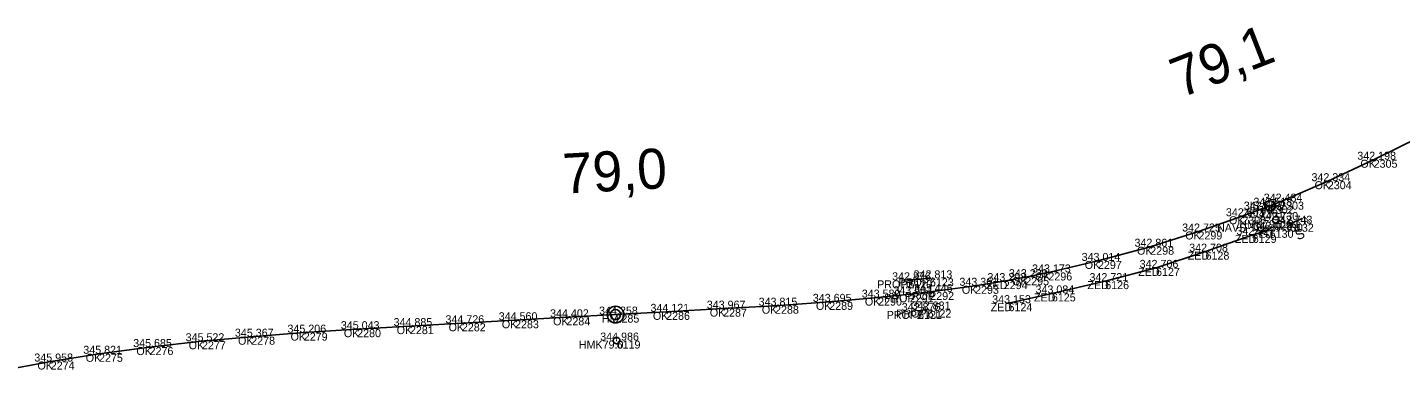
# Model space of a CAD drawing. Extents: x -621782 to -610392, y -1141853 to -1122321.
# Drawn here: x -615402.5 to -615196.7, y -1130069.9 to -1130018.3 of the extents above; entities that cross this region are included whole.
import ezdxf

# ---------------------------------------------------------------- set-up
doc = ezdxf.new("R2010")
doc.units = 0
for name, color, linetype in [('Vrstva 1', 7, 'Continuous'), ('Vrstva 13', 7, 'Continuous'), ('Vrstva 19', 7, 'Continuous'), ('Vrstva 6', 7, 'Continuous'), ('Vrstva 60', 7, 'Continuous'), ('Vrstva 61', 7, 'Continuous'), ('Vrstva 62', 7, 'Continuous'), ('Vrstva 7', 7, 'Continuous')]:
    doc.layers.add(name, color=color, linetype=linetype)

msp = doc.modelspace()

# ---------------------------------------------------------------- linework, layer by layer
at = {"layer": 'Vrstva 1'}
msp.add_lwpolyline([(-615407.12, -1130069.91), (-615399.04, -1130068.4), (-615391.8, -1130067.24), (-615384.22, -1130066.23), (-615376.37, -1130065.36), (-615368.98, -1130064.68), (-615361.1, -1130064.07), (-615353.1, -1130063.55), (-615345.19, -1130063.09), (-615337.4, -1130062.66), (-615329.43, -1130062.21), (-615321.73, -1130061.77), (-615314.37, -1130061.36), (-615306.78, -1130060.95), (-615298.24, -1130060.47), (-615290.45, -1130060.03), (-615282.33, -1130059.45), (-615275, -1130058.81), (-615270.25, -1130058.31), (-615267.18, -1130057.97), (-615260.46, -1130057.04), (-615256.16, -1130056.34), (-615252.94, -1130055.75), (-615249.47, -1130055.04), (-615242.04, -1130053.31), (-615234.2, -1130051.18), (-615226.97, -1130048.9), (-615220.41, -1130046.61), (-615217.74, -1130045.61), (-615216.28, -1130045.04), (-615214.73, -1130044.42), (-615207.58, -1130041.35), (-615200.71, -1130038.13), (-615193.76, -1130034.67)], dxfattribs=at)
at = {"layer": 'Vrstva 13'}
msp.add_lwpolyline([(-615216.29, -1130048.64), (-615218.84, -1130049.41), (-615225.91, -1130051.92), (-615233.33, -1130054.35), (-615240.95, -1130056.34), (-615248.95, -1130058.18), (-615255.45, -1130059.65)], dxfattribs=at)
at = {"layer": 'Vrstva 19'}
for p, q in [((-615270.45, -1130056.22), (-615267.23, -1130055.92)), ((-615269.01, -1130060.81), (-615267.59, -1130060.6))]:
    msp.add_line(p, q, dxfattribs=at)
at = {"layer": 'Vrstva 6'}
for p, q in [((-615211.43, -1130046.95), (-615213.25, -1130047.73)), ((-615213.45, -1130047.27), (-615213.05, -1130048.19))]:
    msp.add_line(p, q, dxfattribs=at)
at = {"layer": 'Vrstva 60'}
for p, q in [((-615200.71, -1130038.13), (-615200.71, -1130038.13)), ((-615207.58, -1130041.35), (-615207.58, -1130041.35)), ((-615216.28, -1130045.04), (-615216.28, -1130045.04)), ((-615214.73, -1130044.42), (-615214.73, -1130044.42)), ((-615220.41, -1130046.61), (-615220.41, -1130046.61)), ((-615217.74, -1130045.61), (-615217.74, -1130045.61)), ((-615226.97, -1130048.9), (-615226.97, -1130048.9)), ((-615216.29, -1130048.64), (-615216.29, -1130048.64)), ((-615215.37, -1130047.18), (-615215.37, -1130047.18)), ((-615213.25, -1130047.73), (-615213.25, -1130047.73)), ((-615234.2, -1130051.18), (-615234.2, -1130051.18)), ((-615218.84, -1130049.41), (-615218.84, -1130049.41)), ((-615242.04, -1130053.31), (-615242.04, -1130053.31)), ((-615225.91, -1130051.92), (-615225.91, -1130051.92)), ((-615249.47, -1130055.04), (-615249.47, -1130055.04)), ((-615233.33, -1130054.35), (-615233.33, -1130054.35)), ((-615270.45, -1130056.22), (-615270.45, -1130056.22)), ((-615267.23, -1130055.92), (-615267.23, -1130055.92)), ((-615260.46, -1130057.04), (-615260.46, -1130057.04)), ((-615256.16, -1130056.34), (-615256.16, -1130056.34)), ((-615252.94, -1130055.75), (-615252.94, -1130055.75)), ((-615240.95, -1130056.34), (-615240.95, -1130056.34)), ((-615282.33, -1130059.45), (-615282.33, -1130059.45)), ((-615275, -1130058.81), (-615275, -1130058.81)), ((-615270.25, -1130058.31), (-615270.25, -1130058.31)), ((-615267.18, -1130057.97), (-615267.18, -1130057.97)), ((-615248.95, -1130058.18), (-615248.95, -1130058.18)), ((-615314.37, -1130061.36), (-615314.37, -1130061.36)), ((-615306.78, -1130060.95), (-615306.78, -1130060.95)), ((-615298.24, -1130060.47), (-615298.24, -1130060.47)), ((-615290.45, -1130060.03), (-615290.45, -1130060.03)), ((-615269.01, -1130060.81), (-615269.01, -1130060.81)), ((-615267.59, -1130060.6), (-615267.59, -1130060.6)), ((-615255.45, -1130059.65), (-615255.45, -1130059.65)), ((-615353.1, -1130063.55), (-615353.1, -1130063.55)), ((-615345.19, -1130063.09), (-615345.19, -1130063.09)), ((-615337.4, -1130062.66), (-615337.4, -1130062.66)), ((-615329.43, -1130062.21), (-615329.43, -1130062.21)), ((-615321.73, -1130061.77), (-615321.73, -1130061.77)), ((-615376.37, -1130065.36), (-615376.37, -1130065.36)), ((-615368.98, -1130064.68), (-615368.98, -1130064.68)), ((-615361.1, -1130064.07), (-615361.1, -1130064.07)), ((-615314.2, -1130065.26), (-615314.2, -1130065.26)), ((-615391.8, -1130067.24), (-615391.8, -1130067.24)), ((-615384.22, -1130066.23), (-615384.22, -1130066.23)), ((-615399.04, -1130068.4), (-615399.04, -1130068.4))]:
    msp.add_line(p, q, dxfattribs=at)
at = {"layer": 'Vrstva 7'}
for p, q in [((-615215.42, -1130047.19), (-615215.33, -1130047.16)), ((-615314.25, -1130065.26), (-615314.15, -1130065.25))]:
    msp.add_line(p, q, dxfattribs=at)
for centre, radius in [((-615216.28, -1130045.04), 0.75), ((-615215.37, -1130047.18), 0.5), ((-615314.37, -1130061.36), 1.25), ((-615314.37, -1130061.36), 0.752), ((-615314.2, -1130065.26), 0.5)]:
    msp.add_circle(centre, radius, dxfattribs=at)

# ---------------------------------------------------------------- texts
at = {"layer": 'Vrstva 6'}
for s, height, p in [('  A A ', 1, (-615212.86, -1130048.65)), ('S', 1.5, (-615212.1, -1130050.24))]:
    msp.add_text(s, height=height, rotation=23.2247, dxfattribs=at).set_placement(p)
at = {"layer": 'Vrstva 60'}
for s, p in [('2305', (-615200.71, -1130039.33)), ('2304', (-615207.58, -1130042.55)), ('2302', (-615216.28, -1130046.24)), ('2303', (-615214.73, -1130045.62)), ('2300', (-615220.41, -1130047.81)), ('2301', (-615217.74, -1130046.81)), ('6131', (-615215.37, -1130048.38)), ('2299', (-615226.97, -1130050.09)), ('6130', (-615216.29, -1130049.84)), ('6132', (-615213.25, -1130048.93)), ('2298', (-615234.2, -1130052.38)), ('6129', (-615218.84, -1130050.61)), ('2297', (-615242.04, -1130054.51)), ('6128', (-615225.91, -1130053.12)), ('2296', (-615249.47, -1130056.24)), ('6127', (-615233.33, -1130055.55)), ('6120', (-615270.45, -1130057.42)), ('6123', (-615267.23, -1130057.12)), ('2293', (-615260.46, -1130058.24)), ('2294', (-615256.16, -1130057.54)), ('2295', (-615252.94, -1130056.95)), ('6126', (-615240.95, -1130057.54)), ('2289', (-615282.33, -1130060.65)), ('2290', (-615275, -1130060.01)), ('2291', (-615270.25, -1130059.51)), ('2292', (-615267.18, -1130059.17)), ('6125', (-615248.95, -1130059.38)), ('2285', (-615314.37, -1130062.56)), ('2286', (-615306.78, -1130062.15)), ('2287', (-615298.24, -1130061.67)), ('2288', (-615290.45, -1130061.23)), ('6121', (-615269.01, -1130062.01)), ('6122', (-615267.59, -1130061.8)), ('6124', (-615255.45, -1130060.85)), ('2280', (-615353.1, -1130064.75)), ('2281', (-615345.19, -1130064.29)), ('2282', (-615337.4, -1130063.86)), ('2283', (-615329.43, -1130063.41)), ('2284', (-615321.73, -1130062.97)), ('2277', (-615376.37, -1130066.56)), ('2278', (-615368.98, -1130065.88)), ('2279', (-615361.1, -1130065.27)), ('6119', (-615314.2, -1130066.46)), ('2275', (-615391.8, -1130068.44)), ('2276', (-615384.22, -1130067.43)), ('2274', (-615399.04, -1130069.6))]:
    msp.add_text(s, height=1.2, dxfattribs=at).set_placement(p)
at = {"layer": 'Vrstva 61'}
for s, p in [('342.198', (-615203.16, -1130038.13)), ('342.334', (-615210.03, -1130041.35)), ('342.552', (-615220.18, -1130045.61)), ('342.518', (-615218.73, -1130045.04)), ('342.484', (-615217.19, -1130044.42)), ('342.603', (-615222.86, -1130046.61)), ('342.730', (-615217.82, -1130047.18)), ('342.743', (-615215.7, -1130047.73)), ('342.725', (-615229.42, -1130048.9)), ('342.527', (-615221.29, -1130049.41)), ('343.028', (-615218.74, -1130048.64)), ('342.861', (-615236.56, -1130051.18)), ('342.708', (-615228.36, -1130051.92)), ('343.014', (-615244.49, -1130053.31)), ('342.706', (-615235.79, -1130054.35)), ('342.876', (-615272.9, -1130056.22)), ('342.813', (-615269.68, -1130055.92)), ('343.293', (-615258.61, -1130056.34)), ('343.239', (-615255.39, -1130055.75)), ('343.173', (-615251.92, -1130055.04)), ('342.721', (-615243.31, -1130056.34)), ('343.503', (-615272.7, -1130058.31)), ('343.446', (-615269.63, -1130057.97)), ('343.361', (-615262.81, -1130057.04)), ('343.084', (-615251.4, -1130058.18)), ('343.967', (-615300.69, -1130060.47)), ('343.815', (-615292.91, -1130060.03)), ('343.695', (-615284.79, -1130059.45)), ('343.580', (-615277.45, -1130058.81)), ('342.881', (-615269.95, -1130060.6)), ('343.153', (-615257.9, -1130059.65)), ('344.726', (-615339.86, -1130062.66)), ('344.560', (-615331.88, -1130062.21)), ('344.402', (-615324.18, -1130061.77)), ('344.258', (-615316.83, -1130061.36)), ('344.121', (-615309.13, -1130060.95)), ('342.876', (-615271.46, -1130060.81)), ('345.367', (-615371.43, -1130064.68)), ('345.206', (-615363.55, -1130064.07)), ('345.043', (-615355.55, -1130063.55)), ('344.885', (-615347.64, -1130063.09)), ('345.685', (-615386.68, -1130066.23)), ('345.522', (-615378.82, -1130065.36)), ('344.986', (-615316.66, -1130065.26)), ('345.958', (-615401.5, -1130068.4)), ('345.821', (-615394.16, -1130067.24))]:
    msp.add_text(s, height=1.2, dxfattribs=at).set_placement(p)
at = {"layer": 'Vrstva 62'}
for s, p in [('OK', (-615202.7, -1130039.33)), ('OK', (-615209.56, -1130042.55)), ('IS-NAV', (-615219.31, -1130045.62)), ('HM', (-615218.31, -1130046.24)), ('OK', (-615222.39, -1130047.81)), ('HMK79.1', (-615220.85, -1130048.38)), ('ZED', (-615220.41, -1130046.81)), ('OK', (-615228.95, -1130050.09)), ('NAVS-Tišnov-130', (-615224.18, -1130048.93)), ('ZED', (-615218.96, -1130049.84)), ('OK', (-615236.19, -1130052.38)), ('ZED', (-615221.51, -1130050.61)), ('OK', (-615244.02, -1130054.51)), ('ZED', (-615228.58, -1130053.12)), ('OK', (-615251.46, -1130056.24)), ('ZED', (-615236.01, -1130055.55)), ('PROPZ', (-615275.15, -1130057.42)), ('PROPZ', (-615271.93, -1130057.12)), ('OK', (-615262.44, -1130058.24)), ('ZED', (-615258.83, -1130057.54)), ('OK', (-615254.92, -1130056.95)), ('ZED', (-615243.62, -1130057.54)), ('OK', (-615284.32, -1130060.65)), ('OK', (-615276.98, -1130060.01)), ('PROP', (-615274.08, -1130059.51)), ('PROP', (-615271.02, -1130059.17)), ('ZED', (-615251.62, -1130059.38)), ('HM', (-615316.41, -1130062.56)), ('OK', (-615308.76, -1130062.15)), ('OK', (-615300.23, -1130061.67)), ('OK', (-615292.43, -1130061.23)), ('PROPZ', (-615273.71, -1130062.01)), ('PROPZ', (-615272.29, -1130061.8)), ('ZED', (-615258.12, -1130060.85)), ('OK', (-615355.09, -1130064.75)), ('OK', (-615347.17, -1130064.29)), ('OK', (-615339.39, -1130063.86)), ('OK', (-615331.41, -1130063.41)), ('OK', (-615323.72, -1130062.97)), ('OK', (-615378.36, -1130066.56)), ('OK', (-615370.96, -1130065.88)), ('OK', (-615363.08, -1130065.27)), ('HMK79.0', (-615319.87, -1130066.46)), ('OK', (-615393.79, -1130068.44)), ('OK', (-615386.2, -1130067.43)), ('OK', (-615401.03, -1130069.6))]:
    msp.add_text(s, height=1.2, dxfattribs=at).set_placement(p)
at = {"layer": 'Vrstva 7'}
for s, rotation, p in [('79,1', 21.3054, (-615229.66, -1130028.92)), ('79,0', 3.2035, (-615322.11, -1130043.23))]:
    msp.add_text(s, height=6, rotation=rotation, dxfattribs=at).set_placement(p)

doc.saveas('drawing.dxf')
